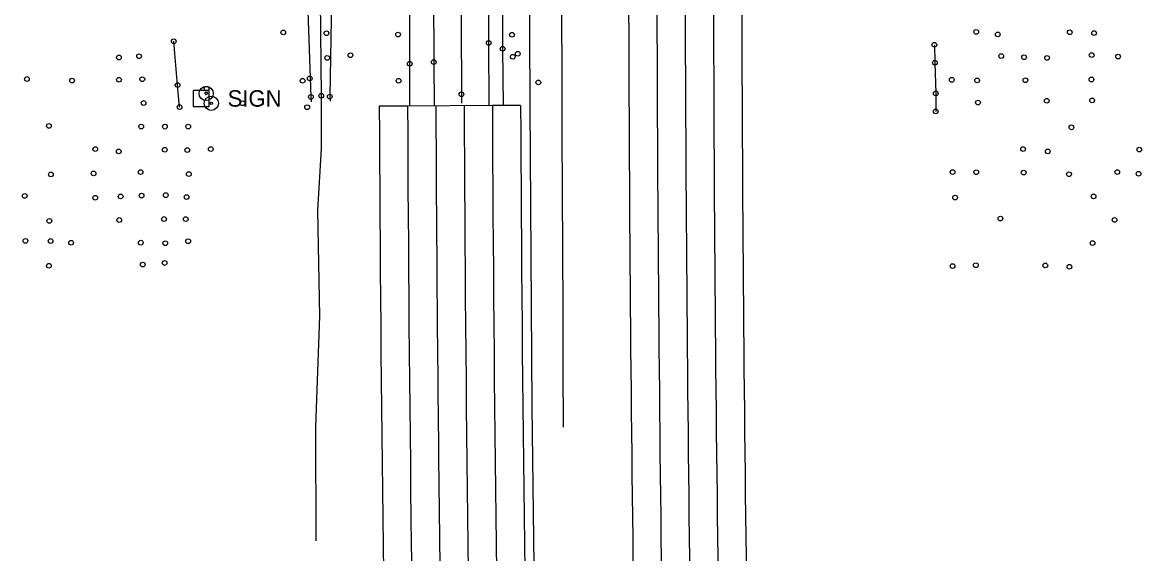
# Model space of a CAD drawing. Extents: x 20503438 to 20508873, y 7964251 to 7984667.
# Drawn here: x 20506381.1 to 20506856.2, y 7965011.6 to 7965237.1 of the extents above; entities that cross this region are included whole.
import ezdxf

# ---------------------------------------------------------------- set-up
doc = ezdxf.new("R2010")
doc.units = 0
for name, color, linetype in [('SurBreakLine', 7, 'Continuous'), ('SurDrainageArrowDown', 7, 'Continuous'), ('SurEdgeRoadPaved', 7, 'Continuous'), ('SurEdgeShoulderPaved', 7, 'Continuous'), ('SurGuardPost', 7, 'Continuous'), ('SurGuardRailCable', 7, 'Continuous'), ('SurPointsNonDTM', 7, 'Continuous'), ('SurRoadPoints', 7, 'Continuous'), ('SurSurveyPoints', 7, 'Continuous')]:
    doc.layers.add(name, color=color, linetype=linetype)

msp = doc.modelspace()

# ---------------------------------------------------------------- linework, layer by layer
at = {"layer": 'SurBreakLine'}
for points in [[(20506522.39, 7965700.71), (20506522, 7965700.32), (20506516.56, 7965699.39), (20506518.84, 7965688.49), (20506515.01, 7965666.88), (20506518.2, 7965645.46), (20506516.16, 7965620.24), (20506516.31, 7965594.85), (20506513.79, 7965556.99), (20506516.81, 7965535.24), (20506512.19, 7965510.34), (20506515.52, 7965469.48), (20506513.97, 7965437.92), (20506507.59, 7965402.71), (20506508.3, 7965381.45), (20506507.78, 7965365.83), (20506514.49, 7965332.27), (20506511.48, 7965277.77), (20506512.31, 7965246.93), (20506511.6, 7965205.59), (20506511.79, 7965203.63)], [(20506511.46, 7965619.33), (20506503.35, 7965594.08), (20506502.22, 7965565.46), (20506501.65, 7965541.77), (20506499.26, 7965511.13), (20506503.71, 7965452.81), (20506496.96, 7965436.26), (20506501.03, 7965397.95), (20506501.18, 7965380.68), (20506501.43, 7965365.34), (20506503.7, 7965327.33), (20506501.82, 7965279.54), (20506502.13, 7965245.82), (20506503.57, 7965205.44), (20506503.7, 7965203.31)], [(20506569.39, 7965603.88), (20506569.1, 7965572.92), (20506568.45, 7965536.8), (20506568.27, 7965501.17), (20506567.94, 7965466.14), (20506567.58, 7965426.78), (20506567.45, 7965405.97), (20506567.32, 7965385.16), (20506567.23, 7965349.31), (20506567.21, 7965328.34), (20506567.14, 7965277.73), (20506567.21, 7965265.93), (20506567.51, 7965206.56), (20506567.54, 7965202.77)]]:
    msp.add_lwpolyline(points, dxfattribs=at)
for radius, start, end in [(22877.31, 179.763399, 181.192225), (22865.31, 179.763399, 181.192225), (22971.31, 180.263424, 180.713399), (22959.31, 180.263424, 181.192225), (22971.31, 180.713399, 181.192225)]:
    msp.add_arc((20529527.68, 7965307.24), radius, start, end, dxfattribs=at)
at = {"layer": 'SurDrainageArrowDown'}
for points in [[(20506512.75, 7965618.39), (20506508.94, 7965594.99), (20506507.21, 7965554.81), (20506510.03, 7965559.76), (20506507.85, 7965536.13), (20506505.57, 7965510.38), (20506511, 7965469.31), (20506507.78, 7965437.68), (20506504.95, 7965403.63), (20506505.01, 7965379.53), (20506507.03, 7965330.13), (20506506.23, 7965279.25), (20506507.51, 7965246.68), (20506507.98, 7965205.94), (20506507.99, 7965183.58), (20506506.45, 7965157.25), (20506507.19, 7965112.35), (20506505.61, 7965065.42), (20506505.71, 7965016.95)], [(20506610.82, 7965065.24), (20506610.71, 7965090.24), (20506610.61, 7965115.23), (20506610.51, 7965140.23), (20506610.41, 7965165.23), (20506610.31, 7965190.23), (20506610.21, 7965215.23), (20506610.1, 7965240.23), (20506610, 7965265.23), (20506609.9, 7965290.23), (20506609.8, 7965315.23), (20506609.7, 7965340.23), (20506609.6, 7965365.23), (20506609.54, 7965378.43)]]:
    msp.add_lwpolyline(points, dxfattribs=at)
at = {"layer": 'SurEdgeRoadPaved'}
msp.add_line((20506580.61, 7965201.74), (20506544.61, 7965201.58), dxfattribs=at)
for points in [[(20506562.98, 7966069.12), (20506561.69, 7965956.65), (20506561.36, 7965927.21), (20506561.02, 7965904.12), (20506560.12, 7965843.51), (20506559.8, 7965821.05), (20506559.37, 7965785.5), (20506558.21, 7965668.14), (20506558.03, 7965647.17), (20506557.54, 7965608.72), (20506556.5, 7965506.31), (20506555.98, 7965462.45), (20506555.76, 7965426.25), (20506555.55, 7965390.53), (20506555.55, 7965365.32), (20506555.55, 7965323.6), (20506555.42, 7965283.68), (20506555.63, 7965249), (20506555.73, 7965220.22), (20506555.85, 7965201.63)], [(20506579.33, 7965201.74), (20506579.06, 7965228.35), (20506578.95, 7965259.46), (20506579.02, 7965289.12), (20506579.03, 7965292.09), (20506578.95, 7965330.25), (20506579.12, 7965400.3), (20506579.58, 7965475.25), (20506579.7, 7965495.86), (20506579.77, 7965507.64), (20506580.77, 7965579.04), (20506582.18, 7965713.39), (20506584.15, 7965857.73), (20506584.51, 7965883.12), (20506584.95, 7965922.01), (20506585.27, 7965953.21), (20506585.61, 7965985.81), (20506586.02, 7966017.66)]]:
    msp.add_lwpolyline(points, dxfattribs=at)
for centre, major_axis, start_param, end_param in [((20529528.35, 7965306.75), (16385.16, -15983.87), 3.910449, 3.935387), ((20529528.35, 7965306.75), (16358.96, -15959.17), 3.910476, 3.935414), ((20529528.36, 7965306.74), (16558.35, -15940.23), 3.912555, 3.928766), ((20529528.36, 7965306.74), (16528.72, -15919.1), 3.912787, 3.928998)]:
    msp.add_ellipse(centre, major_axis=major_axis, ratio=0.999988, start_param=start_param, end_param=end_param, dxfattribs=at)
at = {"layer": 'SurEdgeShoulderPaved'}
for p, q in [((20506544.61, 7965201.58), (20506532.61, 7965201.52)), ((20506592.61, 7965201.8), (20506580.61, 7965201.74))]:
    msp.add_line(p, q, dxfattribs=at)
for points in [[(20506592.19, 7966059.31), (20506591.79, 7966030.9), (20506591.18, 7965975.25), (20506590.93, 7965954.62), (20506589.59, 7965843.55), (20506588.16, 7965735.35), (20506587.68, 7965699.72), (20506587.42, 7965658.24), (20506587.16, 7965625.38), (20506586.88, 7965601.51), (20506586.38, 7965556.01), (20506585.73, 7965519.42), (20506585.6, 7965482.7), (20506584.9, 7965409.44), (20506584.81, 7965350.17), (20506584.84, 7965327.41), (20506584.92, 7965304.74), (20506584.98, 7965265.69), (20506584.99, 7965225.89), (20506585.23, 7965201.77)], [(20506545.59, 7965201.59), (20506545.55, 7965219.53), (20506545.56, 7965256.58), (20506545.28, 7965284.63), (20506545.36, 7965320.45), (20506545.43, 7965347.11), (20506545.59, 7965423.56), (20506545.77, 7965452.03), (20506546.43, 7965505.49), (20506546.86, 7965559.32), (20506548.13, 7965680.05), (20506548.89, 7965738.14), (20506549.41, 7965796.65), (20506550.26, 7965848.19), (20506551.65, 7965956.18), (20506552.19, 7965996.51), (20506552.57, 7966028.45), (20506552.68, 7966057.72)]]:
    msp.add_lwpolyline(points, dxfattribs=at)
for centre, major_axis, start_param, end_param in [((20529528.35, 7965306.75), (16351.94, -15949.18), 3.910378, 3.935316), ((20529528.36, 7965306.74), (16567.63, -15947.9), 3.912515, 3.928726), ((20529528.36, 7965306.74), (16522.29, -15908.48), 3.912648, 3.928859)]:
    msp.add_ellipse(centre, major_axis=major_axis, ratio=0.999988, start_param=start_param, end_param=end_param, dxfattribs=at)
at = {"layer": 'SurGuardPost'}
for points in [[(20506447.83, 7965201.15), (20506447.02, 7965210.45), (20506445.41, 7965229.05)], [(20506768.22, 7965227.55), (20506768.45, 7965219.95), (20506768.84, 7965206.91), (20506768.8, 7965199.29)]]:
    msp.add_lwpolyline(points, dxfattribs=at)
at = {"layer": 'SurGuardRailCable'}
msp.add_lwpolyline([(20506613.34, 7964252.79), (20506601.5, 7964822.04), (20506598.64, 7964984.08), (20506597.55, 7965074.02), (20506596.61, 7965201.81), (20506594.34, 7965701.8), (20506594.71, 7965733.27), (20506595.45, 7965806.52), (20506596.03, 7965869.84), (20506597.23, 7965978.92), (20506600.18, 7966186.78), (20506601.51, 7966279.91), (20506601.63, 7966286.68)], dxfattribs=at)
at = {"layer": 'SurPointsNonDTM'}
for centre in [(20506445.41, 7965229.05), (20506768.22, 7965227.55), (20506591.41, 7965223.76), (20506768.45, 7965219.95), (20506503.13, 7965213.28), (20506447.02, 7965210.45), (20506459.31, 7965208.92), (20506474.59, 7965202.78), (20506768.84, 7965206.91), (20506447.83, 7965201.15), (20506502.01, 7965201.03), (20506768.8, 7965199.29)]:
    msp.add_circle(centre, 1, dxfattribs=at)
at = {"layer": 'SurRoadPoints'}
msp.add_lwpolyline([(20506457.04, 7965201.37), (20506457.04, 7965201.37), (20506460.47, 7965201.37), (20506460.47, 7965208.23), (20506453.61, 7965208.23), (20506453.61, 7965201.37), (20506457.04, 7965201.37)], dxfattribs=at)
for centre, radius in [((20506459.14, 7965206.89), 3), ((20506461.32, 7965202.72), 3), ((20506459.14, 7965206.89), 0.5), ((20506461.32, 7965202.72), 0.5)]:
    msp.add_circle(centre, radius, dxfattribs=at)
at = {"layer": 'SurSurveyPoints'}
for centre in [(20506491.86, 7965232.82), (20506510.21, 7965232.47), (20506540.58, 7965231.9), (20506588.93, 7965231.84), (20506785.98, 7965233.04), (20506795.16, 7965231.97), (20506825.7, 7965232.87), (20506836.02, 7965232.56), (20506579.06, 7965228.35), (20506422.11, 7965222.17), (20506430.65, 7965222.68), (20506510.51, 7965222.02), (20506520.36, 7965223.15), (20506584.99, 7965225.89), (20506589.29, 7965222.5), (20506796.62, 7965222.78), (20506806.34, 7965222.27), (20506816.05, 7965221.98), (20506835, 7965223.2), (20506846.23, 7965222.54), (20506545.55, 7965219.53), (20506555.73, 7965220.22), (20506383.07, 7965213.04), (20506402.21, 7965212.35), (20506422.14, 7965212.73), (20506432.04, 7965212.96), (20506500.09, 7965212.27), (20506540.78, 7965212.28), (20506775.62, 7965212.69), (20506786.38, 7965212.43), (20506806.87, 7965212.53), (20506834.92, 7965212.83), (20506600.13, 7965211.56), (20506432.58, 7965202.85), (20506503.57, 7965205.44), (20506507.98, 7965205.94), (20506511.6, 7965205.59), (20506567.51, 7965206.56), (20506786.75, 7965203.04), (20506815.91, 7965203.79), (20506835.2, 7965203.93), (20506392.41, 7965193.13), (20506431.57, 7965192.87), (20506441.62, 7965192.81), (20506451.52, 7965192.86), (20506826.43, 7965192.53), (20506412.08, 7965183.28), (20506461.1, 7965183.27), (20506805.88, 7965183.31), (20506422.03, 7965182.31), (20506441.57, 7965183.03), (20506451.11, 7965182.89), (20506816.37, 7965182.32), (20506855.2, 7965183.07), (20506393.21, 7965172.55), (20506411.33, 7965172.97), (20506431.32, 7965173.53), (20506451.78, 7965172.66), (20506775.97, 7965173.52), (20506786.01, 7965173.47), (20506806.14, 7965173.3), (20506825.38, 7965172.64), (20506845.87, 7965173.53), (20506854.91, 7965172.8), (20506382.13, 7965163.42), (20506412.06, 7965162.6), (20506422.84, 7965163.18), (20506431.71, 7965163.54), (20506442, 7965163.73), (20506450.8, 7965162.94), (20506777.04, 7965162.73), (20506835.8, 7965163.2), (20506392.57, 7965152.83), (20506422.25, 7965153.18), (20506441.25, 7965153.61), (20506450.46, 7965153.56), (20506796.25, 7965153.81), (20506844.75, 7965153.24), (20506382.42, 7965144.32), (20506393.11, 7965144.27), (20506401.83, 7965143.54), (20506431.4, 7965143.56), (20506441.78, 7965143.35), (20506451.5, 7965144.2), (20506835.37, 7965143.41), (20506392.41, 7965133.74), (20506432.23, 7965134.25), (20506441.51, 7965134.94), (20506775.95, 7965133.63), (20506785.83, 7965133.99), (20506815.33, 7965133.93), (20506825.54, 7965133.32)]:
    msp.add_circle(centre, 1, dxfattribs=at)

# ---------------------------------------------------------------- texts
at = {"layer": 'SurRoadPoints'}
msp.add_text('SIGN', height=6.995, rotation=360, dxfattribs=at).set_placement((20506468.25, 7965201.3))

doc.saveas('drawing.dxf')
